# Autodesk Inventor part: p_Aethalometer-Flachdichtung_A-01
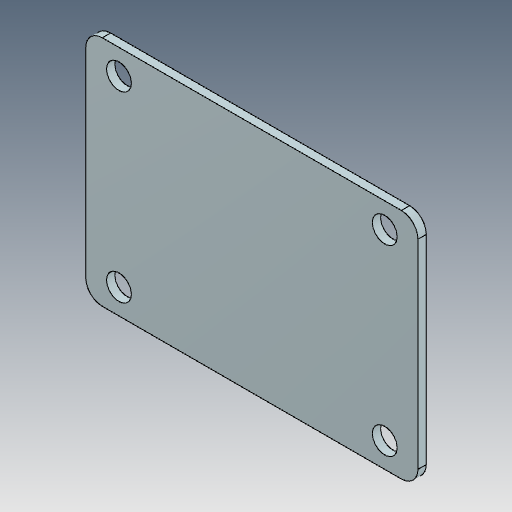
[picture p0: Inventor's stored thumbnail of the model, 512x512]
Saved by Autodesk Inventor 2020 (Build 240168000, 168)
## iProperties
Created: 2020-07
Part Number: p_Aethalometer-Flachdichtung_A-01
Material: Generisch
Document SubType Name: Modeling
Designer: Joshua Backlund
Density: 1 g/cm^3
Appearance: Vorgabe
Author: Joshua Backlund
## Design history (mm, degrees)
feature "Basis1"
feature "Basis2"
node "Volumenkörper1"
node "Volumenkörper2"
